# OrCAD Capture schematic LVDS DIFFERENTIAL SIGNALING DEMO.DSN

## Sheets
1 Differential pair demo: size A0
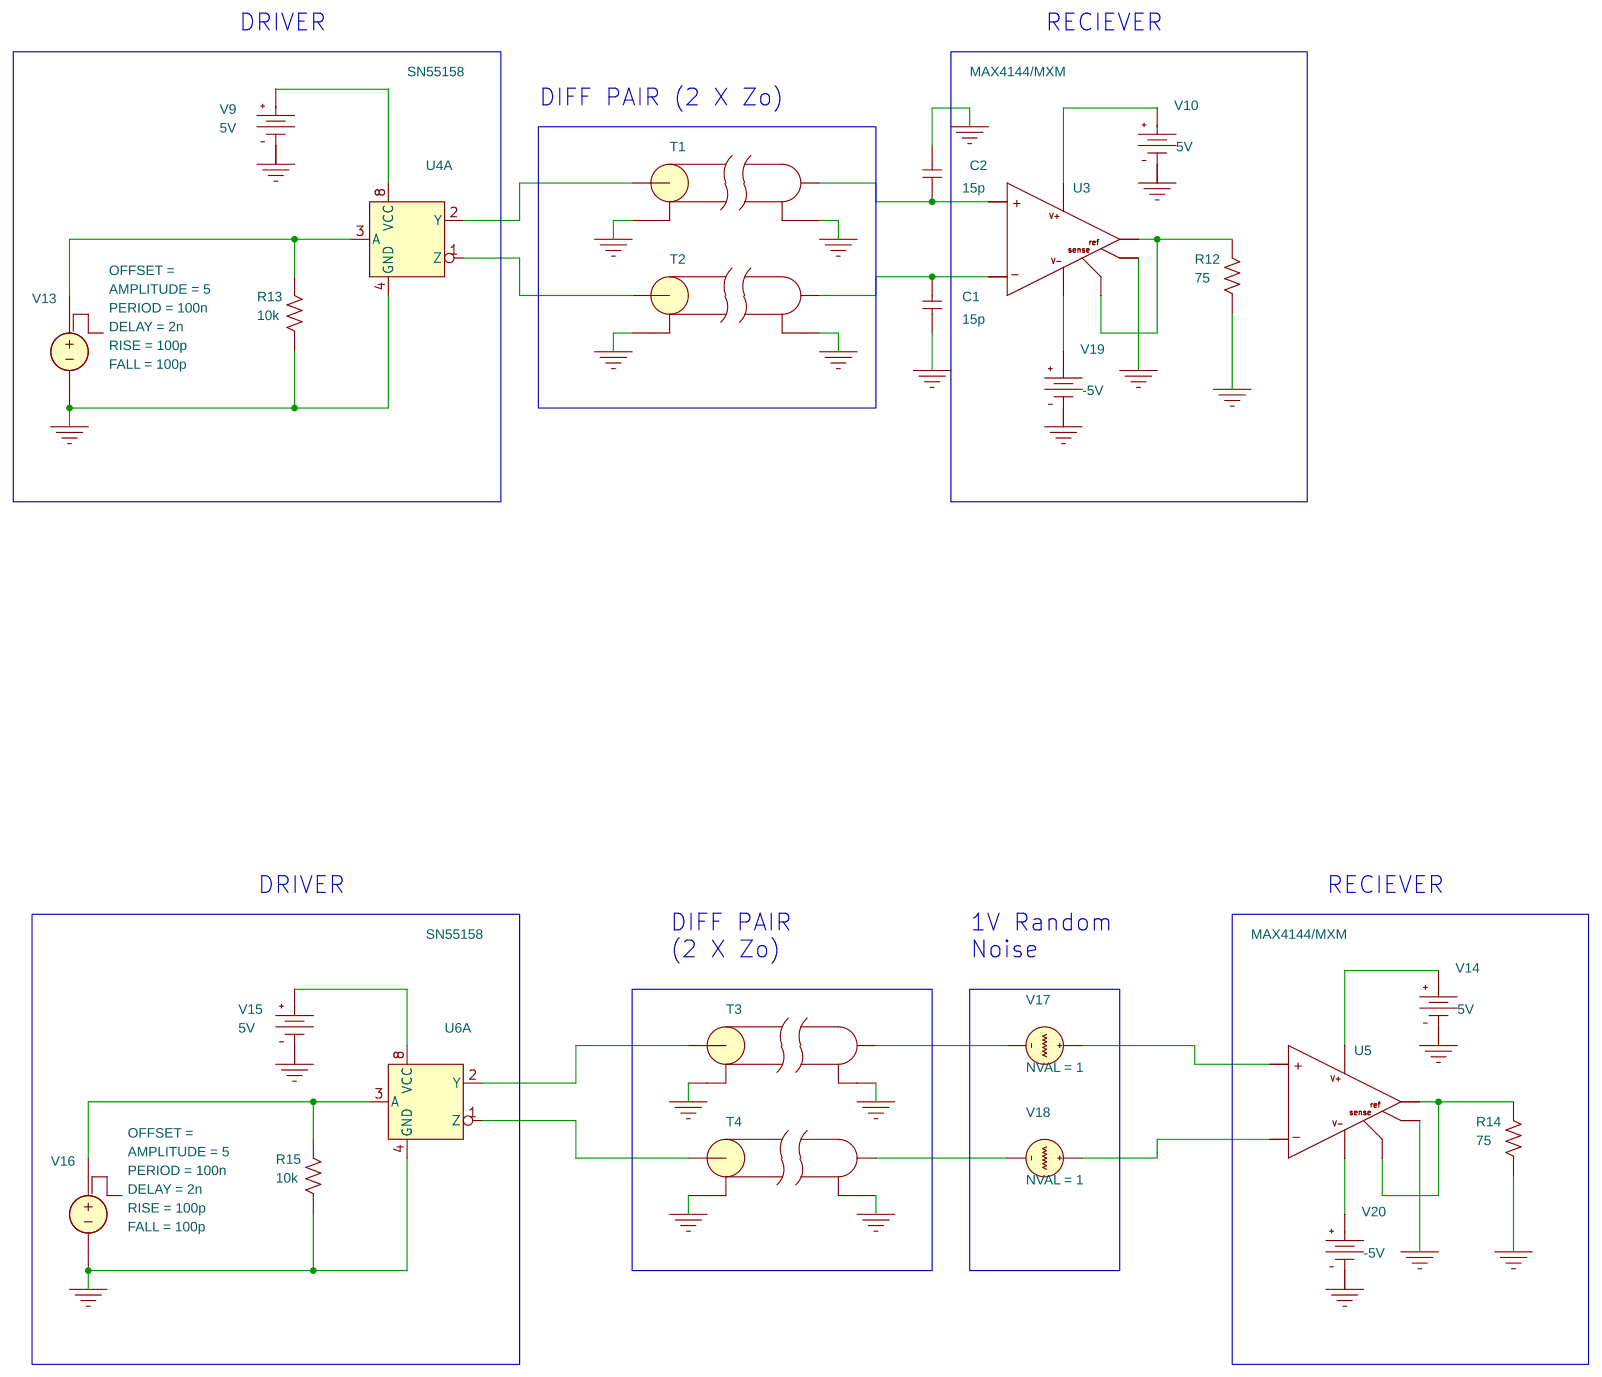
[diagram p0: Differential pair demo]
2 LVDS Demo (incomplete): size A0
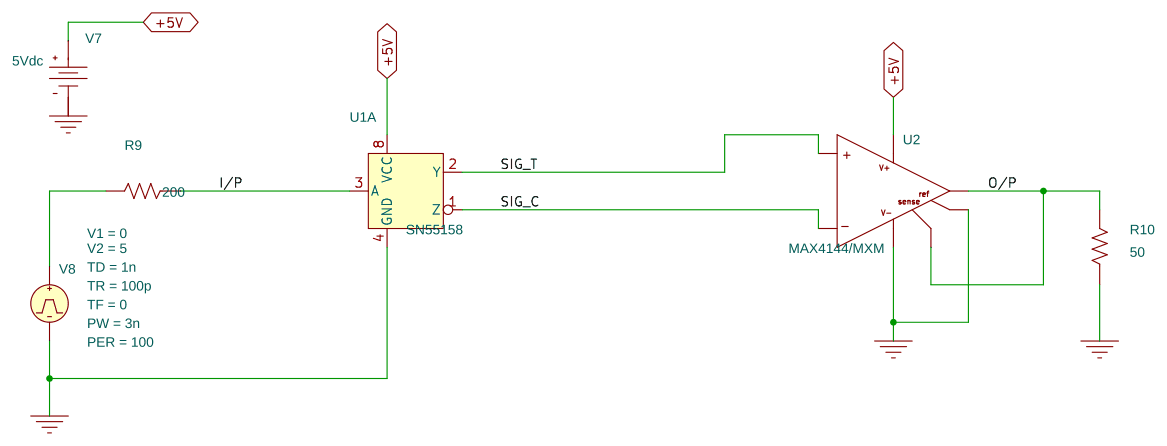
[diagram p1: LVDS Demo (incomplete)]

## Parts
sheet Differential pair demo
C1  15p  [CK05]
C2  15p  [CK05]
R12  75  [RC05]
R13  10k  [RC05]
R14  75  [RC05]
R15  10k  [RC05]
T1  T
T2  T
T3  T
T4  T
U3  MAX4144/MXM
U4  SN55158  [DIP1008W300L425]  (section A)
U5  MAX4144/MXM
U6  SN55158  [DIP1008W300L425]  (section A)
V9  VDC
V10  VDC
V13  ?DC|DC @DC| ?AC|AC @AC|\n+PULSE @OFFSET @AMPLITUDE ?DELAY/@DELAY/~DELAY/0/ #RISE/@RISE/ #FALL/@FALL/ {.5*@PERIOD} #PERIOD/@PERIOD/
V14  VDC
V15  VDC
V16  ?DC|DC @DC| ?AC|AC @AC|\n+PULSE @OFFSET @AMPLITUDE ?DELAY/@DELAY/~DELAY/0/ #RISE/@RISE/ #FALL/@FALL/ {.5*@PERIOD} #PERIOD/@PERIOD/
V17  VAC
V18  VAC
V19  VDC
V20  VDC
sheet LVDS Demo (incomplete)
R9  200  [RC05]
R10  50  [RC05]
U1  SN55158  [DIP1008W300L425]  (section A)
U2  MAX4144/MXM
V7  VDC
V8  VPULSE

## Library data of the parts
C1 C2 = C
R9 R10 R12-R15 = R
T1-T4 = T: TD: 0.1n; Z0: 50
U2 U3 U5 = MAX4144_MXM
U1 U4 U6 = SN55158_0
V9 V10 V14 V15 = VDC: DC: 5V
V13 V16 = V_SQUARE: AMPLITUDE: 5; DELAY: 2n; FALL: 100p; PERIOD: 100n; RISE: 100p
V17 V18 = VRNDMN: AppProp: Noise$Voltage$4$-1; NVAL: 1
V19 V20 = VDC: DC: -5V
V7 = VDC: DC: 5Vdc
V8 = VPULSE: PER: 100; PW: 3n; TD: 1n; TF: 0; TR: 100p; V1: 0; V2: 5

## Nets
+5V: U1.8(VCC) U2.14(V+) V7.0(+)
0: C1.1 C2.2 R10.1 R12.1 R13.1 R14.1 R15.1 T1.2(A-) T1.4(B-) T2.2(A-) T2.4(B-) T3.2(A-) T3.4(B-) T4.2(A-) T4.4(B-) U1.4(GND) U2.1(V-) U2.9(ref) U3.9(ref) U4.4(GND) U5.9(ref) U6.4(GND) V7.1(-) V8.2(-) V9.1(-) V10.1(-) V13.1(NVS) V14.1(-) V15.1(-) V16.1(NVS) V19.1(-) V20.1(-)
I/P: R9.1 U1.3(A)
O/P: R10.2 U2.11(OUT) U2.13(sense)
SIG_C: U1.1(Z) U2.2(-)
SIG_T: U1.2(Y) U2.6(+)
N17670: R9.2 V8.1(+)
N21539: U4.8(VCC) V9.0(+)
N21551: U3.14(V+) V10.0(+)
N21683: R13.2 U4.3(A) V13.2(PVS)
N21701: R12.2 U3.11(OUT) U3.13(sense)
N23407: T1.1(A+) U4.2(Y)
N23419: C2.1 T1.3(B+) U3.6(+)
N23450: T2.1(A+) U4.1(Z)
N23462: C1.2 T2.3(B+) U3.2(-)
N30716: U5.14(V+) V14.0(+)
N30770: U6.8(VCC) V15.0(+)
N30828: T3.1(A+) U6.2(Y)
N30838: U5.6(+) V17.1(+)
N30972: R15.2 U6.3(A) V16.2(PVS)
N31008: R14.2 U5.11(OUT) U5.13(sense)
N31024: T4.1(A+) U6.1(Z)
N31086: U5.2(-) V18.1(+)
N33145: T3.3(B+) V17.2(-)
N33314: T4.3(B+) V18.2(-)
N35380: U3.1(V-) V19.0(+)
N35997: U5.1(V-) V20.0(+)

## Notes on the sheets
sheet 1
- DRIVER
- RECIEVER
- DIFF PAIR (2 X Zo)
- DRIVER
- RECIEVER
- DIFF PAIR
  (2 X Zo)
- 1V Random
  Noise
